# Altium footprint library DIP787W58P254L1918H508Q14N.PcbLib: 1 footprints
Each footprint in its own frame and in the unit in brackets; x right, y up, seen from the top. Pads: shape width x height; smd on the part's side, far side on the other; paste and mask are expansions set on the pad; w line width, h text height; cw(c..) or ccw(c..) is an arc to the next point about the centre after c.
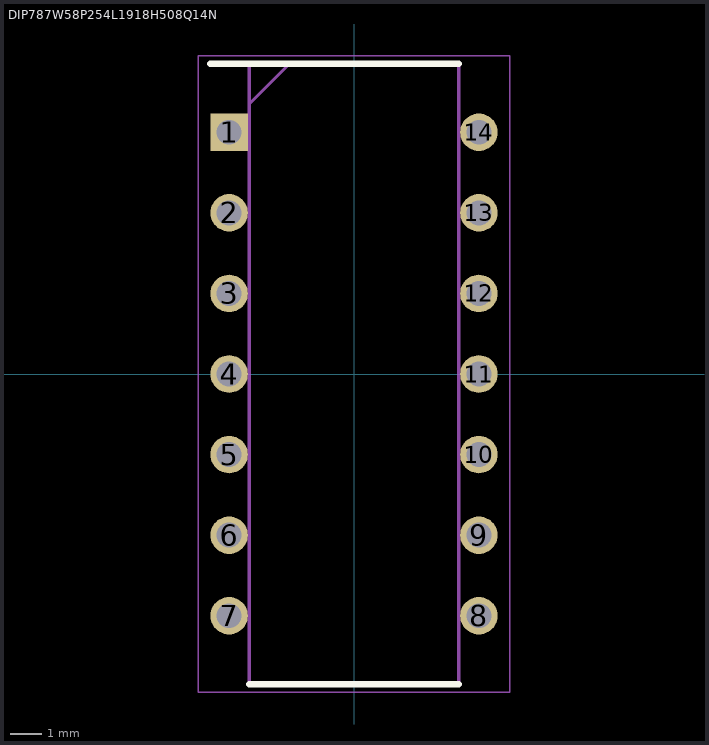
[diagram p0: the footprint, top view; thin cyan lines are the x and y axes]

## DIP787W58P254L1918H508Q14N [mil]
pads (14):
  rect 46.61x46.61 / inner round 46.61 / far side rect 46.61x46.61 hole 30.87: 1(-155,300)
  round 46.61 hole 30.87: 2(-155,200) 3(-155,100) 4(-155,0) 5(-155,-100) 6(-155,-200) 7(-155,-300) 8(155,-300) 9(155,-200) 10(155,-100) 11(155,0) 12(155,100) 13(155,200) 14(155,300)
Top Overlay:
  lines w7.87: -178.31,385.04 130,385.04 ; -130,-385.04 130,-385.04
Mechanical 15:
  lines w3.94: -130,335.04 -80,385.04 ; -130,-385.04 130,-385.04 130,385.04 -130,385.04 -130,-385.04
Mechanical 20:
  lines w1.97: -193.15,-394.88 193.15,-394.88 193.15,394.88 -193.15,394.88 -193.15,-394.88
